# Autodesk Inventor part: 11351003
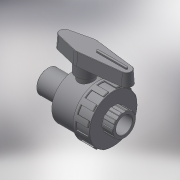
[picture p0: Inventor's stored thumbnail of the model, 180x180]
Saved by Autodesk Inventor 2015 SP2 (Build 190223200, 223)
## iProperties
Created: 2017-11
Part Number: 11351003
Material: Generic
Description: PLASSON 1/NUT VALVE FEMALE THREADED 3/8" PVC
Document SubType Name: Modeling
Designer: KIM
Density: 1 g/cm^3
Appearance: Default
Author: KIM
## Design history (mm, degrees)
derived "113510.ipt"
feature "Solid1::113510.ipt"
tag "TaggingFeature1"
body "Solid1"
other parameters: "d0" = 69, "d2" = 45, "d4" = 11.96, "d8" = 40.5, "d13" = 0.4485, "d25" = 0.299, "d26" = 0.4485, "d29" = 10.5, "d30" = 0, "d35" = 0.4485, "d39" = 22.5, "d45" = 360 deg, "d47" = 0.299, "d50" = 24.75, "d51" = 13.5, "d53" = 0, "d55" = 2.99, "d56" = 1.495, "d57" = 9.8, "d58" = 0, "d59" = 0.4485, "d63" = 18, "d64" = 45, "d66" = 65, "d68" = 9, "d69" = 19.5, "d70" = 11.25, "d71" = 3 deg, "d73" = 0.9, "d74" = 26, "d75" = 1.35, "d76" = 0, "d77" = 0.299, "d78" = 14.95, "d79" = 14, "d80" = 45, "d81" = 14, "d82" = 43.2, "d83" = 9.8, "d84" = 20.93, "d85" = 14.95, "d86" = 20.93, "d87" = 120 deg, "d88" = 14, "d90" = 360 deg, "d92" = 6.75, "d95" = 3.375, "G_" = 14.95, "l_" = 14, "H_" = 69, "K_" = 45, "F_" = 45, "J_" = 65, "d67" = 18, "d72" = 4.5
